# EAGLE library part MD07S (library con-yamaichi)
YAMAICHI CONNECTOR
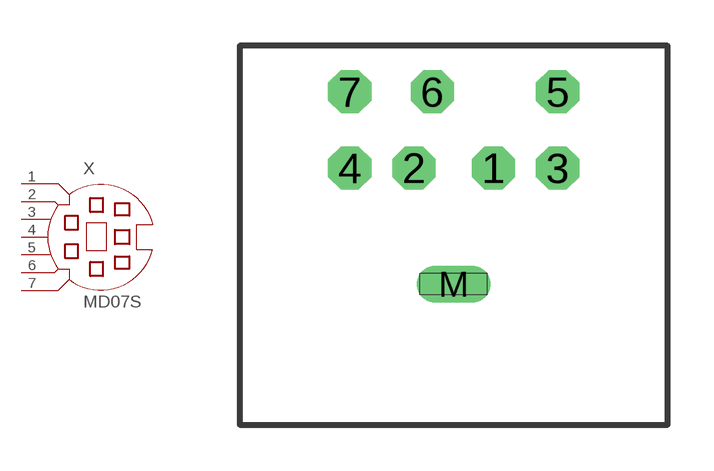
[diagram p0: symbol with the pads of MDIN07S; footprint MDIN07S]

Designator prefix X

## MD07S (OC_FARNELL: unknown; OC_NEWARK: unknown)  [MDIN07S]
1  1  pas
2  2  pas
3  3  pas
4  4  pas
5  5  pas
6  6  pas
7  7  pas

## Footprint MDIN07S (pad centres in mm)
Mini Din YAMAICHI CONNECTOR
drill 0.9 octagon: 1 1.3,8.5; 2 -1.3,8.5; 3 3.4,8.5; 4 -3.4,8.5; 5 3.4,11; 6 -0.7,11; 7 -3.4,11
drill 0.7 long: M 0,4.7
